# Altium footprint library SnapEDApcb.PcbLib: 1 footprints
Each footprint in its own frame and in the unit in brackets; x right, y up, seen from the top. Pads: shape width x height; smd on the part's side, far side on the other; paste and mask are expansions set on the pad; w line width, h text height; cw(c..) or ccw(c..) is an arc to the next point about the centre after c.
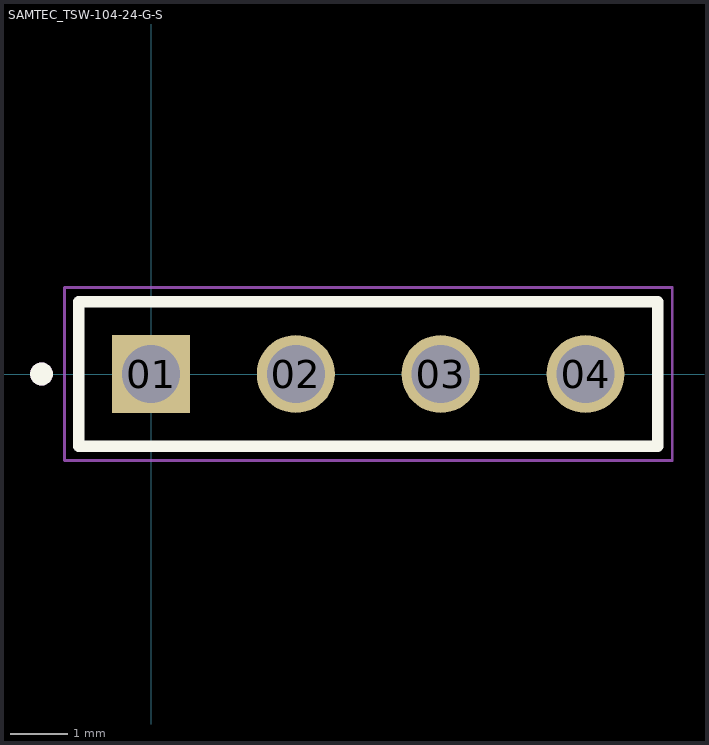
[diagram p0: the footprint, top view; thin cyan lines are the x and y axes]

## SAMTEC_TSW-104-24-G-S [mm]
pads (4):
  rect 1.37x1.37 hole 1.02: 01(0,0)
  round 1.37 hole 1.02: 02(2.54,0) 03(5.08,0) 04(7.62,0)
Top Overlay:
  circle w0.2: c-1.92,0 r0.1
  lines w0.2: -1.27,-1.27 -1.27,1.27 8.89,1.27 8.89,-1.27 -1.27,-1.27
Mechanical 13:
  circle w0.2: c-1.92,0 r0.1
  lines w0.1: -1.27,-1.27 -1.27,1.27 8.89,1.27 8.89,-1.27 -1.27,-1.27
Mechanical 15:
  lines w0.05: -1.52,-1.52 -1.52,1.52 9.14,1.52 9.14,-1.52 -1.52,-1.52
